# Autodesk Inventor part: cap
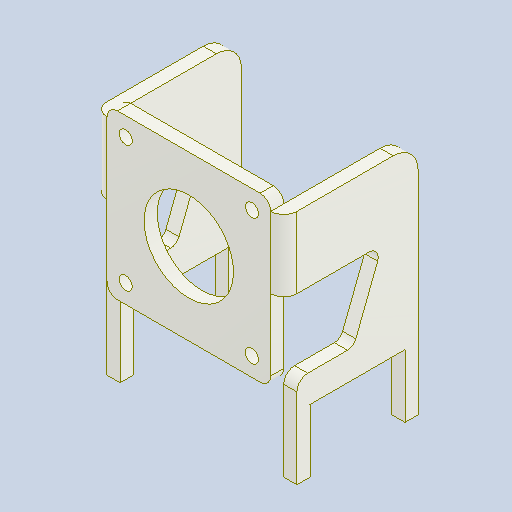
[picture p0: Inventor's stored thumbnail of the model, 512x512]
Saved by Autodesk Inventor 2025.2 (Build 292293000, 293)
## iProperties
Created: 2025-04
Part Number: cap
Material: Generic
Description: PART--DESC
Document SubType Name: Modeling
Designer: BennF
Density: 1 g/cm^3
Appearance: Default
Author: BennF
Revision Number: NONE
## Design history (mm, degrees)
feature "Solid1"
body "Solid2"
